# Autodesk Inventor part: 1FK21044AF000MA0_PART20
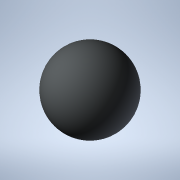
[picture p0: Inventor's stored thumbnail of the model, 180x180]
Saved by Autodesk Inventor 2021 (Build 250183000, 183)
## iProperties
Created: 2025-04
Part Number: 1FK21044AF000MA0_PART20
Material: Generic
Catalog Web Link: www.3dfindit.com
Description: -Servo synchronous motor
Document SubType Name: Modeling
Designer: psAdmin
Mass: 0.137258 g
Surface Area: 1.2868 cm^2
Volume: 0.137258 cm^3
Density: 1 g/cm^3
Appearance: PSOLRGB-212-217-219
Category: PARTsolutions
Title: 1FK21044AF000MA0_PART20
Author: Cadenas PARTsolutions
Comments: Servo synchronous motor
Sending System: PARTsolutions
Preprocessor: ST-DEVELOPER v19.3
PSOL_IDENT_0: {$CADENAS_DATA/23d-libs/siemens_ag/_cat_/39/c4/1fk21044af000ma0.prj},216 {VTYP=3D},{NB=1FK21044AF000
PSOL_IDENT_1: MA0_PART20},{LINA=1FK21044AF000MA0_PART20},{NN=1FK21044AF000MA0_PART20},{NOPRJ=TRUE},{DATE=19.08.202
PSOL_IDENT_2: 5 14:00:33},{GEOMDATE=30.07.2025 02:02:22},{VERSION=},{LINEID=10},{WBVAR=},{WBNUMERIC=}  {NB=1FK2104
PSOL_IDENT_3: 4AF000MA0_PART20},{LINA=1FK21044AF000MA0_PART20},{KT=DUMMY},{PREVIEW=../../../_pool_/cb/72/p_d211_xx
PSOL_IDENT_4: _00434j.png},{DESCSHORT=SIMOTICS S-1FK2 HD, SINAMICS S210 3AC 400V-480V, 1.27 Nm, 3000 rpm},{DESCLON
PSOL_IDENT_5: G=SIMOTICS S-1FK2 HD servo motor M0=1.27 Nm; PN = 0.4 kW at nN=3000 rpm (380-480 V); PN = 0.2 kW at
PSOL_IDENT_6: nN=1500 rpm (200-240 V); degree of protection IP64; cylindrical shaft D19x40mm; absolute encoder 22-
PSOL_IDENT_7: bit + 12-bit multiturn (encoder AM22DQC); with OCC interface; plug size M17, rotatable; SIMOTICS S-1
PSOL_IDENT_8: FK2 servomotorfor a wide range of uses in industrial environments. SIMOTICS S‑1FK2 servomotors are c
PSOL_IDENT_9: ompact synchronous motors with a high dynamic performance that set themselves apart as a result of t
PSOL_IDENT_10: heir high power density, degree of protection and overload capability. The motors are available in t
PSOL_IDENT_11: wo variants: as High Dynamic variant (highest dynamic performance as a result of the low intrinsic m
PSOL_IDENT_12: oment of inertia for applications demanding a high dynamic performance with low moved masses) - and
PSOL_IDENT_13: as Compact variant (precise and stable closed-loop control for medium up to large moved masses as a
PSOL_IDENT_14: result of a medium intrinsic moment of inertia). SIMOTICSS‑1FK2 servomotors fully exploit their stre
PSOL_IDENT_15: ngths in a system with the SINAMICSS210 frequency converter and simple connection using the one cabl
PSOL_IDENT_16: e connection (OCC). Advantages include the short control and positioning times, fast and precise cor
PSOL_IDENT_17: rection of disturbing quantities as well as stable control with a high dynamic performance. The serv
PSOL_IDENT_18: o motors can be configured to address a wide range of requirements. For example with and without hol
PSOL_IDENT_19: ding brake, IP64 or IP65 degree of protection, singleturn or multiturn absolute encoders - to name j
PSOL_IDENT_20: ust a few. Further, the servomotors are available in different shaft heights extending from 20 to 10
PSOL_IDENT_21: 0. A shaft sealing ring is available to achieve an IP65 degree of protection and for subsequent moun
PSOL_IDENT_22: ting at the motor or as spare part. SIMOTICS - the optimum motor for each and every motion control a
PSOL_IDENT_23: pplication.},{INTNO=804766906428},{SUPPLIERALTNO=1FK2104-4AF00-0MA0},{MANUID=1FK21044AF000MA0},{MANU
PSOL_IDENT_24: NAME=Siemens},{MANUTYPEDESC=Synchronous motor 1FK2-HD 1.27 NM},{AAU732=SIMOTICS},{AAO057=S-1FK2},{AA
PSOL_IDENT_25: U734=SIMOTICS S-1FK2 HD servo motor M0=1.27 Nm; PN = 0.4 kW at nN=3000 rpm (380-480 V); PN = 0.2 kW
PSOL_IDENT_26: at nN=1500 rpm (200-240 V); degree of protection IP64; cylindrical shaft D19x40mm; absolute encoder
PSOL_IDENT_27: 22-bit + 12-bit multiturn (encoder AM22DQC); with OCC interface; plug size M17, rotatable;},{AAW338=
PSOL_IDENT_28: Synchronous motor 1FK2-HD 1.27 NM},{AAO742=SIMOTICS},{AAO663=4042948693322},{NOCUPEROU=1},{PRICEQUAN
PSOL_IDENT_29: TITY=1},{QUANTITYMIN=1},{QUANTITYINT=1},{CTN=85015100},{COO=DE},{AAO676=1FK2104-4AF00-0MA0},{AAO677=
PSOL_IDENT_30: Siemens AG},{ORDERUNIT=C62},{CONTENTUNIT=C62}
NB: 1FK21044AF000MA0_PART20
NT: Servo synchronous motor
NBSYN: $MANUID._PART20
LINA: 1FK21044AF000MA0_PART20
CATALOG: SIEMENS
PREVIEW: ../../../_pool_/cb/72/p_d211_xx_00434j.png
DESCSHORT: SIMOTICS S-1FK2 HD, SINAMICS S210 3AC 400V-480V, 1.27 Nm, 3000 rpm
DESCLONG: SIMOTICS S-1FK2 HD servo motor M0=1.27 Nm; PN = 0.4 kW at nN=3000 rpm (380-480 V); PN = 0.2 kW at nN=1500 rpm (200-240 V); degree of protection IP64; cylindrica
INTNO: 804766906428
SUPPLIERALTNO: 1FK2104-4AF00-0MA0
MANUID: 1FK21044AF000MA0
MANUNAME: Siemens
MANUTYPEDESC: Synchronous motor 1FK2-HD 1.27 NM
AAU732: SIMOTICS
AAO057: S-1FK2
AAU734: SIMOTICS S-1FK2 HD servo motor M0=1.27 Nm; PN = 0.4 kW at nN=3000 rpm (380-480 V); PN = 0.2 kW at nN=1500 rpm (200-240 V); degree of protection IP64; cylindrica
AAW338: Synchronous motor 1FK2-HD 1.27 NM
AAO742: SIMOTICS
AAO663: 4042948693322.0
NOCUPEROU: 1
PRICEQUANTITY: 1
QUANTITYMIN: 1
QUANTITYINT: 1
CTN: 85015100
COO: DE
ARTICLENO: 1FK21044AF000MA0_PART20
BOMINFO: 1FK21044AF000MA0_PART20
CREATOR: CADENAS GmbH
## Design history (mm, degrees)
feature "2025_04_17_15_01_28_0038"
body "Solid1"
